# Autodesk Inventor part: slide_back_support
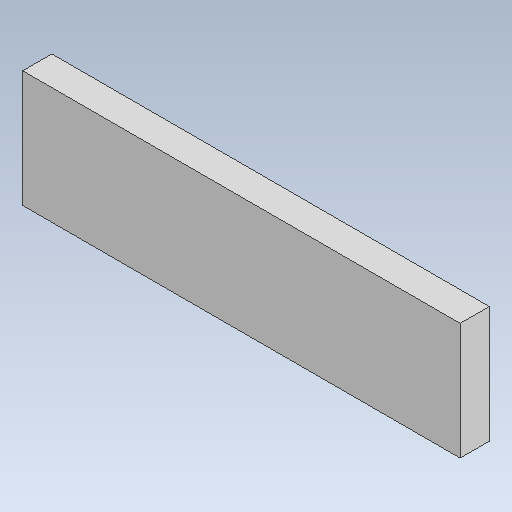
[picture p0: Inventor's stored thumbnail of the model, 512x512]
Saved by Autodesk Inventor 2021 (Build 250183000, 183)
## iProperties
Created: 2026-10
Part Number: slide_back_support
Material: Generic
Document SubType Name: Modeling
Designer: alolo
Density: 1 g/cm^3
Appearance: Default
Author: alolo
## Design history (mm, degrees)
sketch "Sketch1"
  geometry: L1 (0, 0)-(75, 0); L2 (75, 0)-(75, 20); L3 (75, 20)-(0, 20); L4 (0, 20)-(0, 0)
  constraints: 8 end point, 2 parallel, 1 horizontal, 1 perpendicular
  dimensions: "d0" = 75 distance of L3.end L2.end (computed from slide_width); "d1" = 20 distance of L2.end L1.end
extrude "Extrusion1" new body sketch "Sketch1" distance "d2" = 5 (= wood_thickness); taper "d3" = 0 deg
body "Solid1"
other parameters: "slide_length" = 195 [user parameter], "slide_angle" = 7 deg [user parameter], "slide_width" = 65 [user parameter; used in 1 equation term], "wood_thickness" = 5 [user parameter; used in 1 equation term], "aclyric_thickness" = 6 [user parameter]
